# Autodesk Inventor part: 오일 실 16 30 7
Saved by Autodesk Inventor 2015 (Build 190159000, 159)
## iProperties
Created: 2025-11
Part Number: 오일 실 16 30 7
Material: 일반
Document SubType Name: Modeling
Designer: user
Density: 1 g/cm^3
Appearance: 기본값
Author: user
Author: jhkim
Description: 오일-실
Creation Date: 2025-10-31
Sending System: Autodesk Inventor 2026
Preprocessor: ST-DEVELOPER v20.1
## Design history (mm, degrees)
node "오일 실 16 30 71"
body "Solid1"
node "기준1"
